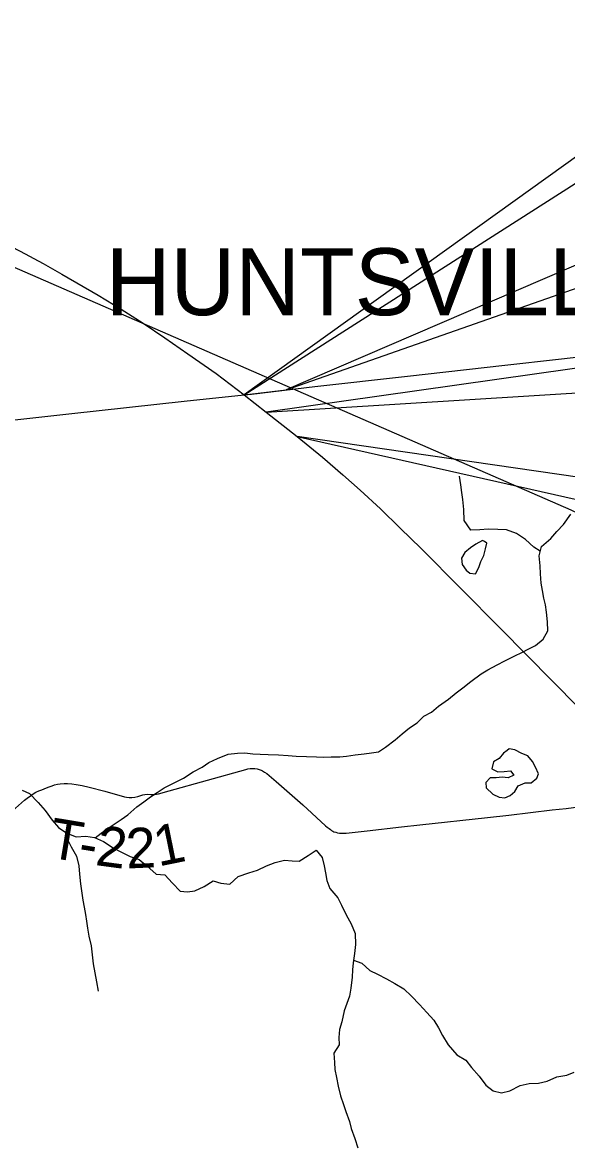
# Model space of a CAD drawing. Extents: x 0 to 34, y -5.4 to 22.
# Drawn here: x 5.117 to 5.887, y 16.492 to 18.075 of the extents above; entities that cross this region are included whole.
import ezdxf

# ---------------------------------------------------------------- set-up
doc = ezdxf.new("R2010")
doc.units = 0
for name, color, linetype in [('GM_X_Corporation_Text', 7, 'Continuous'), ('GM_X_Minor_Lake', 7, 'Continuous'), ('GM_X_Minor_River', 7, 'Continuous'), ('GM_X_Rail_Line', 7, 'Continuous'), ('GM_X_State_Route', 7, 'Continuous'), ('GM_X_Township_Road', 7, 'Continuous'), ('GM_X_Township_Road_Text', 7, 'Continuous'), ('GM_X_US_Route', 7, 'Continuous'), ('SH_Data', 7, 'Continuous')]:
    doc.layers.add(name, color=color, linetype=linetype)

msp = doc.modelspace()

# ---------------------------------------------------------------- linework, layer by layer
at = {"layer": 'GM_X_Minor_Lake'}
for points in [[(5.7695, 17.3407), (5.7669, 17.3422), (5.7573, 17.337), (5.7497, 17.3318), (5.742, 17.3251), (5.7369, 17.3172), (5.7379, 17.3085), (5.7435, 17.3004)], [(5.7435, 17.3004), (5.7488, 17.2961), (5.7567, 17.2953), (5.7614, 17.3043), (5.7645, 17.3126), (5.7685, 17.3213), (5.7712, 17.3304), (5.7729, 17.3387), (5.7695, 17.3407)], [(5.817, 16.9954), (5.827, 16.9994), (5.8357, 16.9997), (5.8437, 17.0064), (5.8457, 17.0124), (5.8417, 17.0216), (5.8373, 17.03), (5.8306, 17.0377), (5.8223, 17.0409), (5.8125, 17.0464), (5.8046, 17.0476), (5.8016, 17.0454)], [(5.8016, 17.0454), (5.7965, 17.0417), (5.7903, 17.0338), (5.7823, 17.0294), (5.7799, 17.0195), (5.7885, 17.0152), (5.7973, 17.0158), (5.8064, 17.0165), (5.8112, 17.0103), (5.8032, 17.0066), (5.7945, 17.0075), (5.7861, 17.0069), (5.7778, 17.0067), (5.7716, 17.0003), (5.7719, 16.9923), (5.7813, 16.9838), (5.7903, 16.9795), (5.7982, 16.9782), (5.8058, 16.9815), (5.8124, 16.9875), (5.817, 16.9954)]]:
    msp.add_lwpolyline(points, dxfattribs=at)
at = {"layer": 'GM_X_Minor_River'}
for points in [[(5.8484, 17.327), (5.8393, 17.3328), (5.8273, 17.3436), (5.8146, 17.3522), (5.8007, 17.3574), (5.7882, 17.358), (5.7746, 17.3582), (5.7632, 17.3573), (5.7504, 17.3571), (5.7407, 17.3705), (5.7402, 17.3861), (5.739, 17.4002), (5.7376, 17.4104), (5.7363, 17.4211), (5.7342, 17.4333)], [(5.2195, 16.9219), (5.2279, 16.9283), (5.2436, 16.9394), (5.2563, 16.9476), (5.2658, 16.9542), (5.2785, 16.9658), (5.2881, 16.9725), (5.2976, 16.9799), (5.3072, 16.9858), (5.3168, 16.9925), (5.3309, 16.9994), (5.3443, 17.0064), (5.358, 17.0153), (5.3706, 17.0219), (5.3802, 17.0282), (5.3924, 17.0341), (5.4076, 17.0399), (5.4205, 17.0416), (5.4307, 17.0418), (5.4424, 17.0408), (5.4527, 17.0403), (5.464, 17.0397), (5.4787, 17.0391), (5.492, 17.0381), (5.5037, 17.0375), (5.5181, 17.0369), (5.5321, 17.0363), (5.5419, 17.0361), (5.5529, 17.0363), (5.565, 17.0365), (5.5748, 17.0375), (5.5866, 17.0392), (5.5995, 17.0408), (5.6097, 17.0418), (5.62, 17.0435), (5.6299, 17.0498), (5.6433, 17.0606), (5.6533, 17.0688), (5.6637, 17.0773), (5.6744, 17.0844), (5.684, 17.0937), (5.6947, 17.0996), (5.7047, 17.1078), (5.7188, 17.1181), (5.7296, 17.1267), (5.7391, 17.1341), (5.7503, 17.143), (5.7648, 17.1538), (5.7744, 17.1593), (5.7877, 17.1663), (5.7984, 17.1722), (5.8125, 17.1792), (5.8221, 17.184), (5.832, 17.1891), (5.8415, 17.1939), (5.8527, 17.2028), (5.8589, 17.2145), (5.8587, 17.2274), (5.8571, 17.2411), (5.8557, 17.2513), (5.8536, 17.2608), (5.8515, 17.2715), (5.8498, 17.2818), (5.8485, 17.2951), (5.8483, 17.3065), (5.847, 17.3205), (5.8499, 17.3338), (5.8633, 17.3453), (5.8718, 17.355), (5.8811, 17.3651), (5.8915, 17.3794)], [(5.1165, 16.9894), (5.1267, 16.9843), (5.139, 16.9719), (5.149, 16.9604), (5.1586, 16.9469), (5.1675, 16.9365), (5.1795, 16.9284)], [(5.178, 16.9294), (5.1805, 16.9196), (5.1856, 16.9093), (5.193, 16.8959), (5.1965, 16.8821), (5.1971, 16.8704), (5.1988, 16.8567), (5.2004, 16.8434), (5.2022, 16.8335), (5.2039, 16.824), (5.206, 16.8133), (5.2074, 16.8038), (5.2087, 16.7939), (5.2104, 16.7828), (5.2136, 16.7691), (5.2153, 16.7566), (5.2166, 16.7436), (5.219, 16.7311), (5.2215, 16.7181), (5.2235, 16.7052)], [(5.1795, 16.9284), (5.1927, 16.9232), (5.2063, 16.9241), (5.2184, 16.9224), (5.2311, 16.9165), (5.245, 16.9079), (5.2555, 16.902), (5.269, 16.8953), (5.2818, 16.891), (5.2923, 16.8824), (5.3057, 16.8704), (5.3178, 16.8695), (5.3286, 16.8575), (5.3397, 16.8463), (5.3499, 16.8454), (5.3602, 16.8467), (5.3735, 16.853), (5.3862, 16.8611), (5.3971, 16.8579), (5.4099, 16.8565), (5.4214, 16.867), (5.4367, 16.8724), (5.4488, 16.876), (5.4614, 16.8822), (5.4736, 16.887), (5.4869, 16.8902), (5.4979, 16.8892), (5.5077, 16.8887), (5.5203, 16.8968), (5.5318, 16.9046), (5.5403, 16.8942), (5.5432, 16.882), (5.5449, 16.8721), (5.547, 16.8614), (5.551, 16.8504), (5.5625, 16.8369), (5.5676, 16.8266), (5.5742, 16.8128), (5.5812, 16.8001), (5.5866, 16.7864), (5.5875, 16.7712), (5.5858, 16.7583), (5.5841, 16.7451), (5.5831, 16.7352), (5.5826, 16.725), (5.5805, 16.7094), (5.5787, 16.6977), (5.5752, 16.6875), (5.5712, 16.6773), (5.5679, 16.6614), (5.5647, 16.6509), (5.5638, 16.6395), (5.564, 16.6293), (5.5566, 16.6172), (5.5575, 16.6039), (5.5581, 16.5941), (5.5606, 16.583), (5.5627, 16.5708), (5.5662, 16.5571), (5.5702, 16.5449), (5.5738, 16.535), (5.5789, 16.5205), (5.581, 16.5109), (5.5864, 16.4968), (5.5904, 16.4835)], [(5.5845, 16.7486), (5.5962, 16.7445), (5.6077, 16.7344), (5.6182, 16.7289), (5.631, 16.7226), (5.643, 16.7156), (5.6554, 16.7082), (5.6665, 16.6977), (5.6777, 16.6862), (5.6881, 16.675), (5.6982, 16.6638), (5.7044, 16.6531), (5.7103, 16.6424), (5.718, 16.6293), (5.7303, 16.6151), (5.7434, 16.6073), (5.7512, 16.5969), (5.7619, 16.5846), (5.7716, 16.5719), (5.782, 16.5641), (5.7937, 16.5613), (5.8055, 16.5641), (5.82, 16.5714), (5.8325, 16.5743), (5.8458, 16.5748), (5.8579, 16.5776), (5.872, 16.5838), (5.8861, 16.5863), (5.8964, 16.5903)]]:
    msp.add_lwpolyline(points, dxfattribs=at)
at = {"layer": 'GM_X_Rail_Line'}
msp.add_lwpolyline([(2.1, 19.046), (2.5086, 18.8639), (2.5191, 18.86), (3.2213, 18.5539), (4.0144, 18.2052), (4.7357, 17.8926), (4.9545, 17.7944), (5.8917, 17.3857), (5.944, 17.3605), (5.9893, 17.3246), (6.0173, 17.2941), (6.0405, 17.2593), (6.0551, 17.2305), (6.1298, 17.0307)], dxfattribs=at)
at = {"layer": 'GM_X_State_Route'}
msp.add_lwpolyline([(4.9955, 17.5005), (5.1865, 17.5218), (5.3451, 17.5394), (5.4298, 17.5482), (5.4404, 17.5493), (5.5298, 17.56), (5.6607, 17.5749), (5.7984, 17.5904), (5.8742, 17.5989), (5.9694, 17.6094), (6.0044, 17.6133)], dxfattribs=at)
at = {"layer": 'GM_X_Township_Road'}
msp.add_line((5.6038, 16.9319), (5.6524, 16.9373), dxfattribs=at)
for points in [[(5.0982, 16.9561), (5.1196, 16.9749), (5.1234, 16.9781), (5.1279, 16.9814), (5.1317, 16.9839), (5.1358, 16.9862), (5.1398, 16.9881), (5.1442, 16.9899), (5.1474, 16.9912), (5.1507, 16.9926), (5.1543, 16.9939), (5.1585, 16.9955), (5.1621, 16.9967), (5.1662, 16.9977), (5.1698, 16.9982), (5.1756, 16.9986), (5.1804, 16.9987), (5.1865, 16.9983), (5.1927, 16.9974), (5.201, 16.996), (5.2109, 16.9936), (5.2331, 16.9876), (5.2607, 16.9799), (5.2637, 16.9793), (5.2677, 16.9789), (5.2713, 16.9788), (5.2753, 16.9793), (5.2796, 16.9805), (5.2838, 16.9817), (5.287, 16.9827), (5.2898, 16.9833), (5.2935, 16.9835), (5.2982, 16.9833), (5.3009, 16.9833), (5.3036, 16.9833), (5.3062, 16.9837), (5.3088, 16.9842), (5.3239, 16.9881), (5.4324, 17.0184), (5.4353, 17.0192), (5.4386, 17.0197), (5.4416, 17.0199), (5.4451, 17.0198), (5.4482, 17.0193), (5.4511, 17.0186), (5.4538, 17.0176), (5.4561, 17.0164), (5.4589, 17.0148), (5.462, 17.0126), (5.4754, 17.0016), (5.5127, 16.9687), (5.5449, 16.939), (5.5473, 16.937), (5.5499, 16.9348), (5.5518, 16.9334), (5.5536, 16.9324), (5.5551, 16.9314), (5.5569, 16.9305), (5.5594, 16.9296), (5.5621, 16.929), (5.5645, 16.9286), (5.5677, 16.9283), (5.5702, 16.9283), (5.5739, 16.9286), (5.6038, 16.9319)], [(5.6524, 16.9373), (5.6783, 16.9401), (5.774, 16.9505), (5.8039, 16.9538), (5.8654, 16.9612), (5.8849, 16.9635), (5.8955, 16.9648), (5.9005, 16.9657), (5.9058, 16.9668), (5.912, 16.9684), (5.9168, 16.9699), (5.9213, 16.9713), (5.927, 16.9732), (5.9343, 16.9761), (5.943, 16.9801), (5.9634, 16.9907), (5.9981, 17.0092)]]:
    msp.add_lwpolyline(points, dxfattribs=at)
at = {"layer": 'GM_X_US_Route'}
for points in [[(3.532, 18.4478), (3.5914, 18.422), (3.7499, 18.3528), (3.8252, 18.32), (3.941, 18.2697), (4.1735, 18.1684), (4.3734, 18.0813), (4.5219, 18.0164), (4.7167, 17.9313), (4.8532, 17.8719), (4.9739, 17.8194), (5.0157, 17.8001), (5.0561, 17.7807), (5.085, 17.7662), (5.1134, 17.7513), (5.1461, 17.7339), (5.1724, 17.7191), (5.2235, 17.6893), (5.2562, 17.6694), (5.2871, 17.6497), (5.3178, 17.6291), (5.3505, 17.6064), (5.3906, 17.5783), (5.4298, 17.5482)], [(5.4298, 17.5482), (5.4613, 17.524), (5.505, 17.4894), (5.5409, 17.4599), (5.5696, 17.4351), (5.5941, 17.4136), (5.6225, 17.387), (5.6504, 17.3599), (5.6803, 17.3308), (5.7921, 17.2178), (5.9025, 17.1063), (5.9981, 17.0092), (6.0363, 16.9707), (6.0631, 16.9439), (6.0729, 16.934)]]:
    msp.add_lwpolyline(points, dxfattribs=at)
at = {"layer": 'SH_Data'}
for p, q in [((5.4298, 17.5482), (5.4895, 17.5552)), ((5.4298, 17.5482), (5.4613, 17.524)), ((5.4613, 17.524), (5.505, 17.4894))]:
    msp.add_line(p, q, dxfattribs=at)
for points in [[(9.2327, 20.2782), (5.4298, 17.5482), (9.2327, 19.9788)], [(9.2327, 19.1682), (5.4895, 17.5552), (9.2327, 18.8687)], [(9.2327, 18.0581), (5.4613, 17.524), (9.2327, 17.7586)], [(9.2327, 16.948), (5.505, 17.4894), (9.2327, 16.6485)]]:
    msp.add_lwpolyline(points, close=True, dxfattribs=at)

# ---------------------------------------------------------------- texts
at = {"layer": 'GM_X_Corporation_Text'}
msp.add_text('HUNTSVILLE', height=0.0947, rotation=0, dxfattribs=at).set_placement((5.2345, 17.6609))
at = {"layer": 'GM_X_Township_Road_Text'}
for s, rotation, p in [('T', 350.5546, (5.1515, 16.8945)), ('2', 352.3684, (5.2184, 16.8835)), ('2', 2.495, (5.264, 16.8784)), ('1', 11.5594, (5.3087, 16.8811)), ('-', 350.7189, (5.1936, 16.8875))]:
    msp.add_text(s, height=0.0568, rotation=rotation, dxfattribs=at).set_placement(p)

doc.saveas('drawing.dxf')
